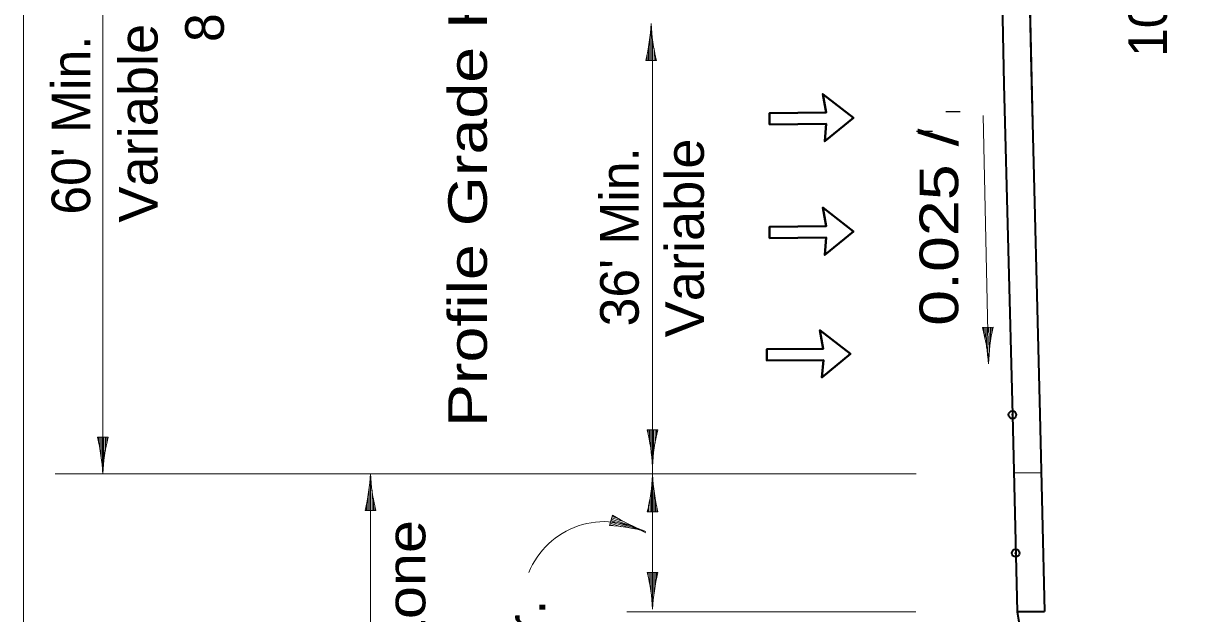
# Model space of a CAD drawing. Extents: x 2363427 to 2368559, y 6957299 to 6980140.
# Drawn here: x 2365735.3 to 2366158.5, y 6961001.1 to 6961215.2 of the extents above; entities that cross this region are included whole.
import ezdxf
from ezdxf.enums import TextEntityAlignment as Align

# ---------------------------------------------------------------- set-up
doc = ezdxf.new("R2010")
doc.units = 0
doc.header["$LTSCALE"] = 5.6
doc.header["$PDMODE"] = 32
doc.header["$PDSIZE"] = 2.8
for name, color, linetype, lineweight in [('3', 7, 'Continuous', 35), ('4', 7, 'Continuous', 13), ('40', 7, 'Continuous', 35), ('8', 7, 'Continuous', 13)]:
    doc.layers.add(name, color=color, linetype=linetype, lineweight=lineweight)

msp = doc.modelspace()

# ---------------------------------------------------------------- linework, layer by layer
at = {"layer": '3'}
for p, q in [((2366097.115, 6961373.231), (2366100.705, 6961193.277)), ((2366100.703, 6961193.339), (2366103.837, 6961073.473)), ((2366093.839, 6961073.212), (2366095.505, 6961001.781)), ((2366103.837, 6961073.445), (2366105.505, 6961001.898)), ((2366105.507, 6961001.781), (2366095.505, 6961001.781)), ((2366095.505, 6961001.781), (2366158.457, 6960639.587))]:
    msp.add_line(p, q, dxfattribs=at)
for points in [[(2366087.117, 6961373.031), (2366090.707, 6961193.078), (2366093.839, 6961073.212)], [(2366093.839, 6961073.212), (2366093.771, 6961073.358), (2366093.839, 6961073.212)]]:
    msp.add_lwpolyline(points, dxfattribs=at)
at = {"layer": '3', "lineweight": 13}
for points in [[(2366094.361, 6961052.185), (2366104.289, 6961052.218), (2366098.175, 6961316.93), (2366087.946, 6961316.604)], [(2366095.505, 6961001.781), (2366105.505, 6961001.898), (2366104.289, 6961052.218), (2366094.361, 6961052.185)]]:
    msp.add_lwpolyline(points, close=True, dxfattribs=at)
at = {"layer": '3'}
for p in [(2366093.839, 6961073.212), (2366095.009, 6961023.061)]:
    msp.add_point(p, dxfattribs=at)
at = {"layer": '4'}
for p, q in [((2365735.289, 6960373.031), (2365735.289, 6961373.031)), ((2365764.135, 6961051.781), (2365764.135, 6961321.781)), ((2365962.913, 6961201.747), (2365962.913, 6961214.311)), ((2365962.413, 6961201.747), (2365962.413, 6961210.357)), ((2365963.413, 6961201.747), (2365963.413, 6961209.097)), ((2365961.413, 6961201.747), (2365961.413, 6961204.129)), ((2365961.913, 6961201.747), (2365961.913, 6961206.609)), ((2365963.913, 6961201.747), (2365963.913, 6961206.023)), ((2365964.413, 6961201.747), (2365964.413, 6961203.332)), ((2365964.763, 6961201.747), (2365960.933, 6961201.747)), ((2365963.407, 6961012.304), (2365963.407, 6961202.429)), ((2365963.351, 6961189.701), (2365963.351, 6961192.213)), ((2366084.911, 6961103.135), (2366083.299, 6961181.755)), ((2366082.991, 6961104.913), (2366086.821, 6961104.991)), ((2366083.341, 6961104.919), (2366083.373, 6961103.335)), ((2366083.841, 6961104.93), (2366083.929, 6961100.655)), ((2366084.341, 6961104.94), (2366084.491, 6961097.592)), ((2366084.841, 6961104.951), (2366085.097, 6961092.389)), ((2366085.341, 6961104.961), (2366085.517, 6961096.353)), ((2366085.841, 6961104.971), (2366085.939, 6961100.11)), ((2366086.341, 6961104.981), (2366086.389, 6961102.6)), ((2365961.435, 6961067.817), (2365965.265, 6961067.817)), ((2365961.785, 6961067.817), (2365961.785, 6961066.231)), ((2365962.285, 6961067.817), (2365962.285, 6961063.54)), ((2365962.785, 6961067.817), (2365962.785, 6961060.467)), ((2365963.285, 6961067.817), (2365963.285, 6961055.253)), ((2365963.785, 6961067.817), (2365963.785, 6961059.207)), ((2365964.285, 6961067.817), (2365964.285, 6961062.955)), ((2365964.785, 6961067.817), (2365964.785, 6961065.435)), ((2365762.171, 6961065.095), (2365766.001, 6961065.095)), ((2365762.521, 6961065.095), (2365762.521, 6961063.51)), ((2365763.021, 6961065.095), (2365763.021, 6961060.819)), ((2365763.521, 6961065.095), (2365763.521, 6961057.745)), ((2365764.021, 6961065.095), (2365764.021, 6961052.531)), ((2365764.521, 6961065.095), (2365764.521, 6961056.485)), ((2365765.021, 6961065.095), (2365765.021, 6961060.233)), ((2365765.521, 6961065.095), (2365765.521, 6961062.713)), ((2366059.005, 6961051.781), (2365746.803, 6961051.781)), ((2365861.117, 6960918.139), (2365861.117, 6961051.781)), ((2365861.183, 6961038.568), (2365861.183, 6961051.132)), ((2365963.473, 6961038.057), (2365963.473, 6961050.621)), ((2365860.683, 6961038.568), (2365860.683, 6961047.177)), ((2365861.683, 6961038.568), (2365861.683, 6961045.918)), ((2365962.973, 6961038.057), (2365962.973, 6961046.667)), ((2365860.183, 6961038.568), (2365860.183, 6961043.43)), ((2365862.183, 6961038.568), (2365862.183, 6961042.845)), ((2365962.473, 6961038.057), (2365962.473, 6961042.919)), ((2365963.973, 6961038.057), (2365963.973, 6961045.407)), ((2365964.473, 6961038.057), (2365964.473, 6961042.333)), ((2365863.033, 6961038.568), (2365859.203, 6961038.568)), ((2365859.683, 6961038.568), (2365859.683, 6961040.949)), ((2365862.683, 6961038.568), (2365862.683, 6961040.153)), ((2365965.323, 6961038.057), (2365961.493, 6961038.057)), ((2365961.973, 6961038.057), (2365961.973, 6961040.439)), ((2365964.973, 6961038.057), (2365964.973, 6961039.642)), ((2365947.721, 6961033.125), (2365948.886, 6961036.773)), ((2365947.827, 6961033.459), (2365949.337, 6961032.976)), ((2365947.979, 6961033.935), (2365952.053, 6961032.633)), ((2365948.131, 6961034.411), (2365955.133, 6961032.175)), ((2365948.283, 6961034.887), (2365960.252, 6961031.064)), ((2365948.435, 6961035.363), (2365956.637, 6961032.743)), ((2365948.588, 6961035.84), (2365953.219, 6961034.361)), ((2365948.74, 6961036.317), (2365951.009, 6961035.591)), ((2365961.493, 6961016.035), (2365965.323, 6961016.035)), ((2365961.843, 6961016.035), (2365961.843, 6961014.449)), ((2365962.343, 6961016.035), (2365962.343, 6961011.758)), ((2365962.843, 6961016.035), (2365962.843, 6961008.685)), ((2365963.343, 6961016.035), (2365963.343, 6961003.471)), ((2365963.843, 6961016.035), (2365963.843, 6961007.425)), ((2365964.343, 6961016.035), (2365964.343, 6961011.173)), ((2365964.843, 6961016.035), (2365964.843, 6961013.653)), ((2366058.865, 6961001.781), (2365954.099, 6961001.781))]:
    msp.add_line(p, q, dxfattribs=at)
at = {"layer": '4', "lineweight": 25}
for p, q in [((2366069.726, 6961183.215), (2366074.907, 6961183.215)), ((2366064.849, 6961175.906), (2366059.058, 6961175.906))]:
    msp.add_line(p, q, dxfattribs=at)
at = {"layer": '4'}
for centre, radius, start, end in [((2365890.725, 6961218.641), 72.212, 346.47039, 357.15644), ((2366034.972, 6961218.641), 72.212, 182.84356, 193.52961), ((2366013.143, 6961086.584), 72.212, 4.01743, 14.70348), ((2366157.36, 6961089.539), 72.212, 167.64427, 178.33032), ((2365891.227, 6961050.923), 72.212, 2.84356, 13.52961), ((2366035.474, 6961050.923), 72.212, 166.47039, 177.15644), ((2365691.963, 6961048.202), 72.212, 2.84356, 13.52961), ((2365836.21, 6961048.202), 72.212, 166.47039, 177.15644), ((2365788.994, 6961055.462), 72.212, 346.47039, 357.15644), ((2365933.241, 6961055.462), 72.212, 182.84356, 193.52961), ((2365891.284, 6961054.951), 72.212, 346.47039, 357.15644), ((2366035.531, 6961054.951), 72.212, 182.84356, 193.52961), ((2365945.964, 6961004.837), 29.635, 59.62074, 157.81619), ((2365986.344, 6961098.512), 72.212, 238.75343, 249.43948), ((2365942.448, 6960961.106), 72.212, 75.12659, 85.81264), ((2365891.284, 6960999.141), 72.212, 2.84356, 13.52961), ((2366035.531, 6960999.141), 72.212, 166.47039, 177.15644)]:
    msp.add_arc(centre, radius, start, end, dxfattribs=at)
at = {"layer": '40'}
for p, q in [((2366026.333, 6961178.718), (2366005.829, 6961178.523)), ((2366026.333, 6961137.503), (2366005.829, 6961137.309)), ((2366025.331, 6961093.077), (2366004.825, 6961092.882))]:
    msp.add_line(p, q, dxfattribs=at)
for points in [[(2366026.333, 6961178.718), (2366025.801, 6961172.403), (2366036.189, 6961180.938), (2366025.089, 6961189.541), (2366026.297, 6961182.813)], [(2366026.297, 6961182.813), (2366005.791, 6961182.618), (2366005.829, 6961178.523)], [(2366026.333, 6961137.503), (2366025.801, 6961131.189), (2366036.189, 6961139.723), (2366025.089, 6961148.326), (2366026.297, 6961141.599)], [(2366026.297, 6961141.599), (2366005.791, 6961141.403), (2366005.829, 6961137.309)], [(2366025.331, 6961093.077), (2366024.797, 6961086.762), (2366035.185, 6961095.297), (2366024.085, 6961103.899), (2366025.293, 6961097.172)], [(2366025.293, 6961097.172), (2366004.787, 6961096.977), (2366004.825, 6961092.882)]]:
    msp.add_lwpolyline(points, dxfattribs=at)
at = {"layer": '8', "lineweight": 40}
for points in [[(2366036.189, 6961180.938), (2366025.801, 6961172.403), (2366026.333, 6961178.718), (2366005.829, 6961178.523), (2366005.791, 6961182.618), (2366026.297, 6961182.813), (2366025.089, 6961189.541)], [(2366036.189, 6961139.723), (2366025.801, 6961131.189), (2366026.333, 6961137.503), (2366005.829, 6961137.309), (2366005.791, 6961141.403), (2366026.297, 6961141.599), (2366025.089, 6961148.326)], [(2366035.185, 6961095.297), (2366024.797, 6961086.762), (2366025.331, 6961093.077), (2366004.825, 6961092.882), (2366004.787, 6961096.977), (2366025.293, 6961097.172), (2366024.085, 6961103.899)]]:
    msp.add_lwpolyline(points, close=True, dxfattribs=at)

# ---------------------------------------------------------------- texts
at = {"layer": '4'}
for s, p in [("10' Shldr.", (2366149.906, 6961242.218)), ("8' Shldr.", (2365807.971, 6961242.453)), ("60' Min.", (2365759.529, 6961178.288)), ("36' Min.", (2365958.377, 6961137.794)), ("10' Shldr.", (2365924.487, 6960966.77))]:
    msp.add_text(s, height=14, rotation=90, dxfattribs=at).set_placement(p, align=Align.CENTER)
for s, width, p in [('Profile Grade HOV ', 1.25, (2365903.341, 6961169.552)), ('Variable', 1.05, (2365783.941, 6961178.952)), ('0.025 /', 1.25, (2366074.193, 6961141.257)), ('Variable', 1.05, (2365981.985, 6961137.34)), ('Clear Zone', 1.15, (2365881.025, 6960981.804))]:
    msp.add_text(s, height=14, rotation=90, dxfattribs=dict(at, width=width)).set_placement(p, align=Align.CENTER)

doc.saveas('drawing.dxf')
